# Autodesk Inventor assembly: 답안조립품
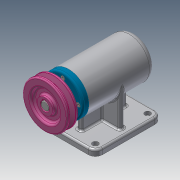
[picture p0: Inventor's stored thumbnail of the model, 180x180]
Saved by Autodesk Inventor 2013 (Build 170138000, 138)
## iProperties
Created: 2020-10
Part Number: 답안조립품
Document SubType Name: Weldment
Designer: CADCOM
Weld Material: Welded Aluminum-6061
Author: CADCOM
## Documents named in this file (12)
- C:\Users\CADCOM\Desktop\701004V1015\답안조립품.iam
- C:\Users\CADCOM\Desktop\701004V1015\본체.ipt
- C:\Users\CADCOM\Desktop\701004V1015\V벨트풀리.ipt
- C:\Users\CADCOM\Desktop\701004V1015\멈춤나사 M3.ipt
- C:\Users\CADCOM\Desktop\701004V1015\베어링 6004.ipt
- C:\Users\CADCOM\Desktop\701004V1015\베어링 51202.ipt
- C:\Users\CADCOM\Desktop\701004V1015\볼트 M4.ipt
- C:\Users\CADCOM\Desktop\701004V1015\어댑터슬리브.ipt
- C:\Users\CADCOM\Desktop\701004V1015\오일 실.ipt
- C:\Users\CADCOM\Desktop\701004V1015\축.ipt
- C:\Users\CADCOM\Desktop\701004V1015\커버.ipt
- C:\Users\CADCOM\Desktop\701004V1015\키 5 x 5 x 16.ipt
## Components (1 placed, 1 different names)
1. V벨트풀리:1 — 플러쉬:1
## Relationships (1: Flush 1)
- 플러쉬:1 [Flush]: V벨트풀리:1
